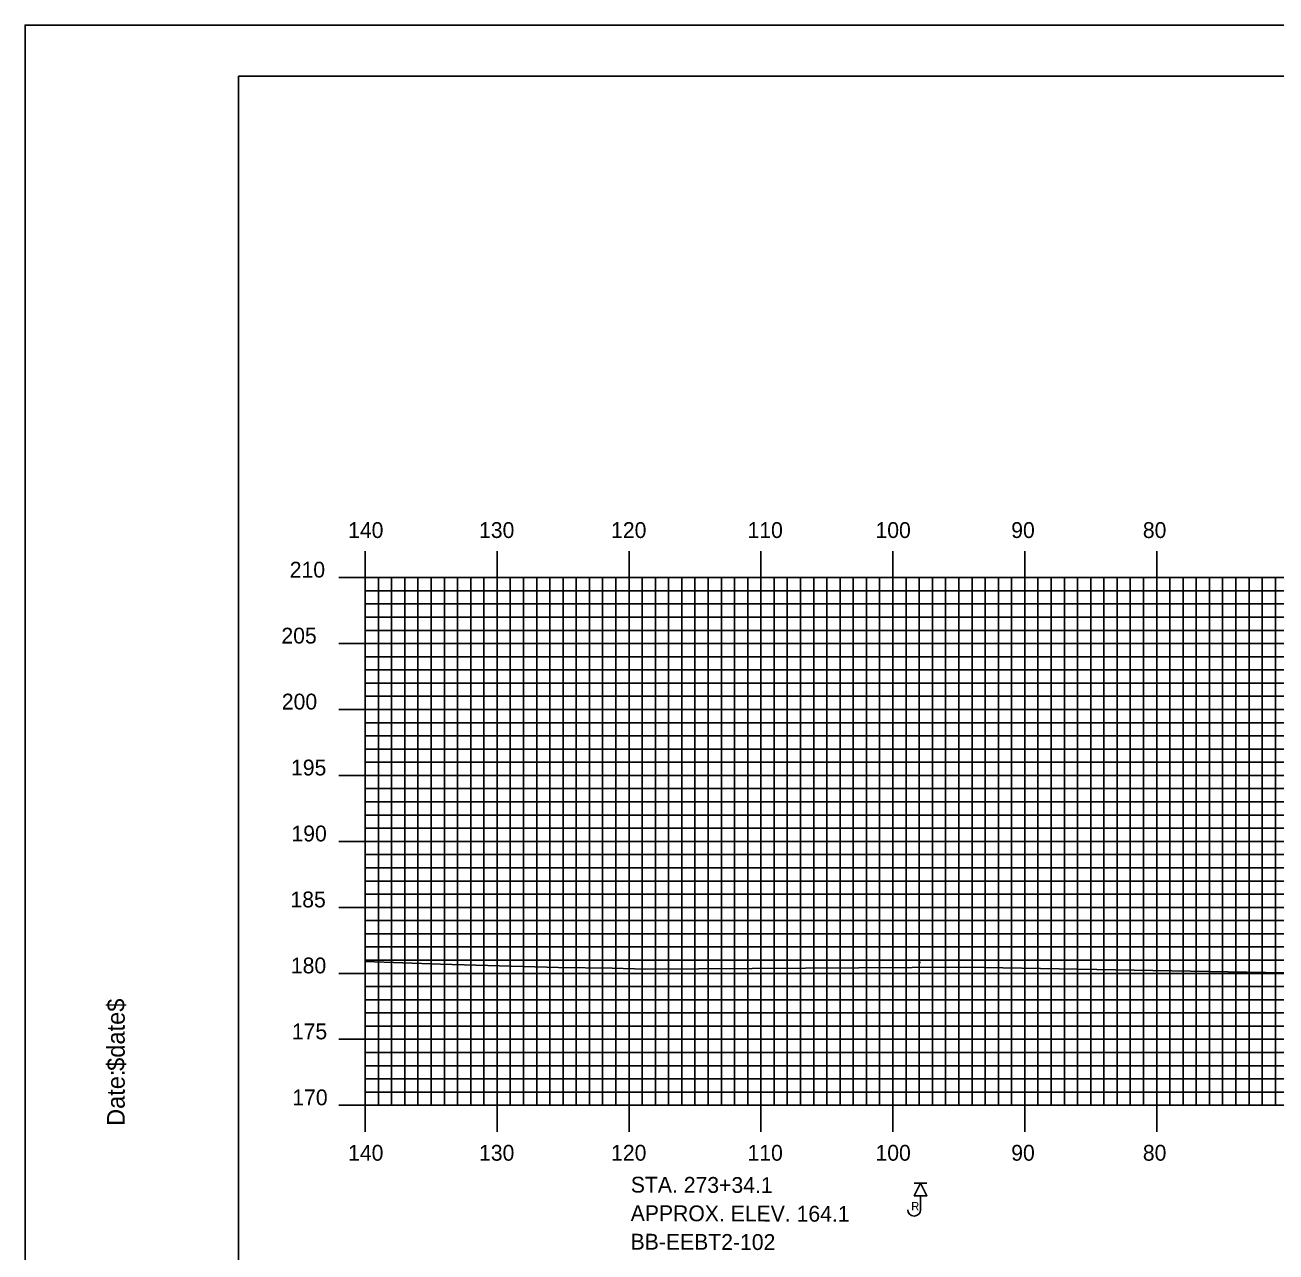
# Model space of a CAD drawing. Extents: x 1809013 to 1809356, y 442591 to 442811.
# Drawn here: x 1809012.5 to 1809107.4, y 442717.5 to 442810.5 of the extents above; entities that cross this region are included whole.
import ezdxf

# ---------------------------------------------------------------- set-up
doc = ezdxf.new("R2010")
doc.units = 0
for name, color, linetype in [('BORDER', 7, 'Continuous'), ('BORING - REFUSAL', 7, 'Continuous'), ('H_V ANNOTATION', 7, 'Continuous'), ('MAJOR', 7, 'Continuous'), ('MINOR', 7, 'Continuous'), ('PLOT BOUNDARY', 7, 'Continuous'), ('S_Property_Well_GroundElevation', 7, 'Continuous'), ('S_Roadway_Centerline', 7, 'Continuous')]:
    doc.layers.add(name, color=color, linetype=linetype)

msp = doc.modelspace()

# ---------------------------------------------------------------- linework, layer by layer
at = {"layer": 'BORDER'}
msp.add_lwpolyline([(1809028.724, 442596.665), (1809348.724, 442596.665), (1809348.724, 442806.665), (1809028.724, 442806.665)], close=True, dxfattribs=at)
at = {"layer": 'BORING - REFUSAL'}
for p, q in [((1809080.904, 442722.765), (1809079.944, 442722.765)), ((1809080.424, 442721.806), (1809080.424, 442720.747))]:
    msp.add_line(p, q, dxfattribs=at)
msp.add_lwpolyline([(1809080.424, 442722.765), (1809080.904, 442721.806), (1809079.944, 442721.806)], close=True, dxfattribs=at)
msp.add_arc((1809079.939, 442720.747), 0.485, 180, 0, dxfattribs=at)
at = {"layer": 'MAJOR'}
for p, q in [((1809038.324, 442770.669), (1809038.324, 442768.665)), ((1809048.324, 442770.669), (1809048.324, 442768.665)), ((1809058.324, 442770.669), (1809058.324, 442768.665)), ((1809068.324, 442770.669), (1809068.324, 442768.665)), ((1809078.324, 442770.669), (1809078.324, 442768.665)), ((1809088.324, 442770.669), (1809088.324, 442768.665)), ((1809098.324, 442770.669), (1809098.324, 442768.665)), ((1809036.32, 442768.665), (1809038.324, 442768.665)), ((1809038.324, 442768.665), (1809318.324, 442768.665)), ((1809038.324, 442728.665), (1809038.324, 442768.665)), ((1809038.324, 442728.665), (1809038.324, 442768.665)), ((1809038.324, 442768.665), (1809318.324, 442768.665)), ((1809048.324, 442728.665), (1809048.324, 442768.665)), ((1809058.324, 442728.665), (1809058.324, 442768.665)), ((1809068.324, 442728.665), (1809068.324, 442768.665)), ((1809078.324, 442728.665), (1809078.324, 442768.665)), ((1809088.324, 442728.665), (1809088.324, 442768.665)), ((1809098.324, 442728.665), (1809098.324, 442768.665)), ((1809036.32, 442763.665), (1809038.324, 442763.665)), ((1809038.324, 442763.665), (1809318.324, 442763.665)), ((1809036.32, 442758.665), (1809038.324, 442758.665)), ((1809038.324, 442758.665), (1809318.324, 442758.665)), ((1809036.32, 442753.665), (1809038.324, 442753.665)), ((1809038.324, 442753.665), (1809318.324, 442753.665)), ((1809036.32, 442748.665), (1809038.324, 442748.665)), ((1809038.324, 442748.665), (1809318.324, 442748.665)), ((1809036.32, 442743.665), (1809038.324, 442743.665)), ((1809038.324, 442743.665), (1809318.324, 442743.665)), ((1809036.32, 442738.665), (1809038.324, 442738.665)), ((1809038.324, 442738.665), (1809318.324, 442738.665)), ((1809036.32, 442733.665), (1809038.324, 442733.665)), ((1809038.324, 442733.665), (1809318.324, 442733.665)), ((1809036.32, 442728.665), (1809038.324, 442728.665)), ((1809038.324, 442728.665), (1809318.324, 442728.665)), ((1809038.324, 442728.665), (1809318.324, 442728.665)), ((1809038.324, 442726.661), (1809038.324, 442728.665)), ((1809048.324, 442726.661), (1809048.324, 442728.665)), ((1809058.324, 442726.661), (1809058.324, 442728.665)), ((1809068.324, 442726.661), (1809068.324, 442728.665)), ((1809078.324, 442726.661), (1809078.324, 442728.665)), ((1809088.324, 442726.661), (1809088.324, 442728.665)), ((1809098.324, 442726.661), (1809098.324, 442728.665))]:
    msp.add_line(p, q, dxfattribs=at)
at = {"layer": 'MINOR'}
for p, q in [((1809039.324, 442728.665), (1809039.324, 442768.665)), ((1809040.324, 442728.665), (1809040.324, 442768.665)), ((1809041.324, 442728.665), (1809041.324, 442768.665)), ((1809042.324, 442728.665), (1809042.324, 442768.665)), ((1809043.324, 442728.665), (1809043.324, 442768.665)), ((1809044.324, 442728.665), (1809044.324, 442768.665)), ((1809045.324, 442728.665), (1809045.324, 442768.665)), ((1809046.324, 442728.665), (1809046.324, 442768.665)), ((1809047.324, 442728.665), (1809047.324, 442768.665)), ((1809049.324, 442728.665), (1809049.324, 442768.665)), ((1809050.324, 442728.665), (1809050.324, 442768.665)), ((1809051.324, 442728.665), (1809051.324, 442768.665)), ((1809052.324, 442728.665), (1809052.324, 442768.665)), ((1809053.324, 442728.665), (1809053.324, 442768.665)), ((1809054.324, 442728.665), (1809054.324, 442768.665)), ((1809055.324, 442728.665), (1809055.324, 442768.665)), ((1809056.324, 442728.665), (1809056.324, 442768.665)), ((1809057.324, 442728.665), (1809057.324, 442768.665)), ((1809059.324, 442728.665), (1809059.324, 442768.665)), ((1809060.324, 442728.665), (1809060.324, 442768.665)), ((1809061.324, 442728.665), (1809061.324, 442768.665)), ((1809062.324, 442728.665), (1809062.324, 442768.665)), ((1809063.324, 442728.665), (1809063.324, 442768.665)), ((1809064.324, 442728.665), (1809064.324, 442768.665)), ((1809065.324, 442728.665), (1809065.324, 442768.665)), ((1809066.324, 442728.665), (1809066.324, 442768.665)), ((1809067.324, 442728.665), (1809067.324, 442768.665)), ((1809069.324, 442728.665), (1809069.324, 442768.665)), ((1809070.324, 442728.665), (1809070.324, 442768.665)), ((1809071.324, 442728.665), (1809071.324, 442768.665)), ((1809072.324, 442728.665), (1809072.324, 442768.665)), ((1809073.324, 442728.665), (1809073.324, 442768.665)), ((1809074.324, 442728.665), (1809074.324, 442768.665)), ((1809075.324, 442728.665), (1809075.324, 442768.665)), ((1809076.324, 442728.665), (1809076.324, 442768.665)), ((1809077.324, 442728.665), (1809077.324, 442768.665)), ((1809079.324, 442728.665), (1809079.324, 442768.665)), ((1809080.324, 442728.665), (1809080.324, 442768.665)), ((1809081.324, 442728.665), (1809081.324, 442768.665)), ((1809082.324, 442728.665), (1809082.324, 442768.665)), ((1809083.324, 442728.665), (1809083.324, 442768.665)), ((1809084.324, 442728.665), (1809084.324, 442768.665)), ((1809085.324, 442728.665), (1809085.324, 442768.665)), ((1809086.324, 442728.665), (1809086.324, 442768.665)), ((1809087.324, 442728.665), (1809087.324, 442768.665)), ((1809089.324, 442728.665), (1809089.324, 442768.665)), ((1809090.324, 442728.665), (1809090.324, 442768.665)), ((1809091.324, 442728.665), (1809091.324, 442768.665)), ((1809092.324, 442728.665), (1809092.324, 442768.665)), ((1809093.324, 442728.665), (1809093.324, 442768.665)), ((1809094.324, 442728.665), (1809094.324, 442768.665)), ((1809095.324, 442728.665), (1809095.324, 442768.665)), ((1809096.324, 442728.665), (1809096.324, 442768.665)), ((1809097.324, 442728.665), (1809097.324, 442768.665)), ((1809099.324, 442728.665), (1809099.324, 442768.665)), ((1809100.324, 442728.665), (1809100.324, 442768.665)), ((1809101.324, 442728.665), (1809101.324, 442768.665)), ((1809102.324, 442728.665), (1809102.324, 442768.665)), ((1809103.324, 442728.665), (1809103.324, 442768.665)), ((1809104.324, 442728.665), (1809104.324, 442768.665)), ((1809105.324, 442728.665), (1809105.324, 442768.665)), ((1809106.324, 442728.665), (1809106.324, 442768.665)), ((1809107.324, 442728.665), (1809107.324, 442768.665)), ((1809038.324, 442767.665), (1809318.324, 442767.665)), ((1809038.324, 442767.665), (1809040.328, 442767.665)), ((1809038.324, 442766.665), (1809318.324, 442766.665)), ((1809038.324, 442766.665), (1809040.328, 442766.665)), ((1809038.324, 442765.665), (1809318.324, 442765.665)), ((1809038.324, 442765.665), (1809040.328, 442765.665)), ((1809038.324, 442764.665), (1809318.324, 442764.665)), ((1809038.324, 442764.665), (1809040.328, 442764.665)), ((1809038.324, 442762.665), (1809318.324, 442762.665)), ((1809038.324, 442762.665), (1809040.328, 442762.665)), ((1809038.324, 442761.665), (1809318.324, 442761.665)), ((1809038.324, 442761.665), (1809040.328, 442761.665)), ((1809038.324, 442760.665), (1809318.324, 442760.665)), ((1809038.324, 442760.665), (1809040.328, 442760.665)), ((1809038.324, 442759.665), (1809318.324, 442759.665)), ((1809038.324, 442759.665), (1809040.328, 442759.665)), ((1809038.324, 442757.665), (1809318.324, 442757.665)), ((1809038.324, 442757.665), (1809040.328, 442757.665)), ((1809038.324, 442756.665), (1809318.324, 442756.665)), ((1809038.324, 442756.665), (1809040.328, 442756.665)), ((1809038.324, 442755.665), (1809318.324, 442755.665)), ((1809038.324, 442755.665), (1809040.328, 442755.665)), ((1809038.324, 442754.665), (1809318.324, 442754.665)), ((1809038.324, 442754.665), (1809040.328, 442754.665)), ((1809038.324, 442752.665), (1809318.324, 442752.665)), ((1809038.324, 442752.665), (1809040.328, 442752.665)), ((1809038.324, 442751.665), (1809318.324, 442751.665)), ((1809038.324, 442751.665), (1809040.328, 442751.665)), ((1809038.324, 442750.665), (1809318.324, 442750.665)), ((1809038.324, 442750.665), (1809040.328, 442750.665)), ((1809038.324, 442749.665), (1809318.324, 442749.665)), ((1809038.324, 442749.665), (1809040.328, 442749.665)), ((1809038.324, 442747.665), (1809318.324, 442747.665)), ((1809038.324, 442747.665), (1809040.328, 442747.665)), ((1809038.324, 442746.665), (1809318.324, 442746.665)), ((1809038.324, 442746.665), (1809040.328, 442746.665)), ((1809038.324, 442745.665), (1809318.324, 442745.665)), ((1809038.324, 442745.665), (1809040.328, 442745.665)), ((1809038.324, 442744.665), (1809318.324, 442744.665)), ((1809038.324, 442744.665), (1809040.328, 442744.665)), ((1809038.324, 442742.665), (1809318.324, 442742.665)), ((1809038.324, 442742.665), (1809040.328, 442742.665)), ((1809038.324, 442741.665), (1809318.324, 442741.665)), ((1809038.324, 442741.665), (1809040.328, 442741.665)), ((1809038.324, 442740.665), (1809318.324, 442740.665)), ((1809038.324, 442740.665), (1809040.328, 442740.665)), ((1809038.324, 442739.665), (1809318.324, 442739.665)), ((1809038.324, 442739.665), (1809040.328, 442739.665)), ((1809038.324, 442737.665), (1809318.324, 442737.665)), ((1809038.324, 442737.665), (1809040.328, 442737.665)), ((1809038.324, 442736.665), (1809318.324, 442736.665)), ((1809038.324, 442736.665), (1809040.328, 442736.665)), ((1809038.324, 442735.665), (1809318.324, 442735.665)), ((1809038.324, 442735.665), (1809040.328, 442735.665)), ((1809038.324, 442734.665), (1809318.324, 442734.665)), ((1809038.324, 442734.665), (1809040.328, 442734.665)), ((1809038.324, 442732.665), (1809318.324, 442732.665)), ((1809038.324, 442732.665), (1809040.328, 442732.665)), ((1809038.324, 442731.665), (1809318.324, 442731.665)), ((1809038.324, 442731.665), (1809040.328, 442731.665)), ((1809038.324, 442730.665), (1809318.324, 442730.665)), ((1809038.324, 442730.665), (1809040.328, 442730.665)), ((1809038.324, 442729.665), (1809318.324, 442729.665)), ((1809038.324, 442729.665), (1809040.328, 442729.665))]:
    msp.add_line(p, q, dxfattribs=at)
at = {"layer": 'PLOT BOUNDARY'}
msp.add_lwpolyline([(1809012.538, 442590.547), (1809352.538, 442590.547), (1809352.538, 442810.547), (1809012.538, 442810.547)], close=True, dxfattribs=at)
at = {"layer": 'S_Property_Well_GroundElevation'}
for p, q in [((1809080.41, 442739.492), (1809080.407, 442739.492)), ((1809080.408, 442739.494), (1809080.408, 442739.491)), ((1809080.409, 442739.491), (1809080.408, 442739.493)), ((1809080.409, 442739.493), (1809080.408, 442739.491))]:
    msp.add_line(p, q, dxfattribs=at)
at = {"layer": 'S_Roadway_Centerline'}
msp.add_lwpolyline([(1809038.324, 442739.567), (1809044.029, 442739.358), (1809052.982, 442739.119), (1809057.045, 442739.069), (1809059.578, 442738.995), (1809083.821, 442739.145), (1809107.986, 442738.706)], dxfattribs=at)

# ---------------------------------------------------------------- texts
at = {"layer": 'BORDER'}
for s, p in [('$date$', (1809020.094, 442731.275)), ('Date:', (1809020.094, 442727.099))]:
    msp.add_text(s, height=1.3392, rotation=90, dxfattribs=at).set_placement(p)
at = {"layer": 'BORING - REFUSAL'}
for s, p in [('STA. 273+34.1', (1809058.458, 442722.05)), ('APPROX. ELEV. 164.1', (1809058.451, 442719.89)), ('BB-EEBT2-102', (1809058.444, 442717.73))]:
    msp.add_text(s, height=1.2, rotation=359.81416, dxfattribs=at).set_placement(p)
msp.add_text('R', height=0.64, dxfattribs=at).set_placement((1809079.715, 442720.691))
at = {"layer": 'H_V ANNOTATION'}
for s, p in [('140', (1809037.029, 442771.665)), ('130', (1809046.954, 442771.665)), ('120', (1809056.965, 442771.665)), ('110', (1809067.307, 442771.665)), ('100', (1809077.008, 442771.665)), ('90', (1809087.297, 442771.665)), ('80', (1809097.275, 442771.665)), ('210', (1809032.605, 442768.665)), ('205', (1809031.973, 442763.665)), ('200', (1809032.005, 442758.665)), ('195', (1809032.702, 442753.665)), ('190', (1809032.734, 442748.665)), ('185', (1809032.659, 442743.665)), ('180', (1809032.691, 442738.665)), ('175', (1809032.766, 442733.665)), ('170', (1809032.798, 442728.665)), ('140', (1809037.029, 442724.465)), ('130', (1809046.954, 442724.465)), ('120', (1809056.965, 442724.465)), ('110', (1809067.307, 442724.465)), ('100', (1809077.008, 442724.465)), ('90', (1809087.297, 442724.465)), ('80', (1809097.275, 442724.465))]:
    msp.add_text(s, height=1.2, dxfattribs=at).set_placement(p)
at = {"layer": 'MAJOR'}
msp.add_text('-', height=0.012, dxfattribs=at).set_placement((1809038.315, 442728.665))
at = {"layer": 'S_Property_Well_GroundElevation'}
msp.add_text('WG', height=0.00583, dxfattribs=at).set_placement((1809080.404, 442739.484))

doc.saveas('drawing.dxf')
